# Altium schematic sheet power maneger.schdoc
size 297 x 209 mm; Symbol: Drawing-Symbol_A4; @Project Name: Hưhwwuey; @Page Count: 1; @Update Date: 2026-09-22; @Create Date: 2026-09-22; @Schematic Name: Schematic1; @Page No: 1; @Page Name: P1; Company: EasyEDA.com; Version: V1.0; Page Size: A4; Device: Drawing-Symbol_A4; @Create Time: 21:23:17; @Update Time: 21:23:17; Border: 1; Width: 1170; Height: 825; Region Start: 1; X Region Count: 6; Y Region Count: 4; Blade Width: 10; Title Block Position: 3; @Board Name: Board1
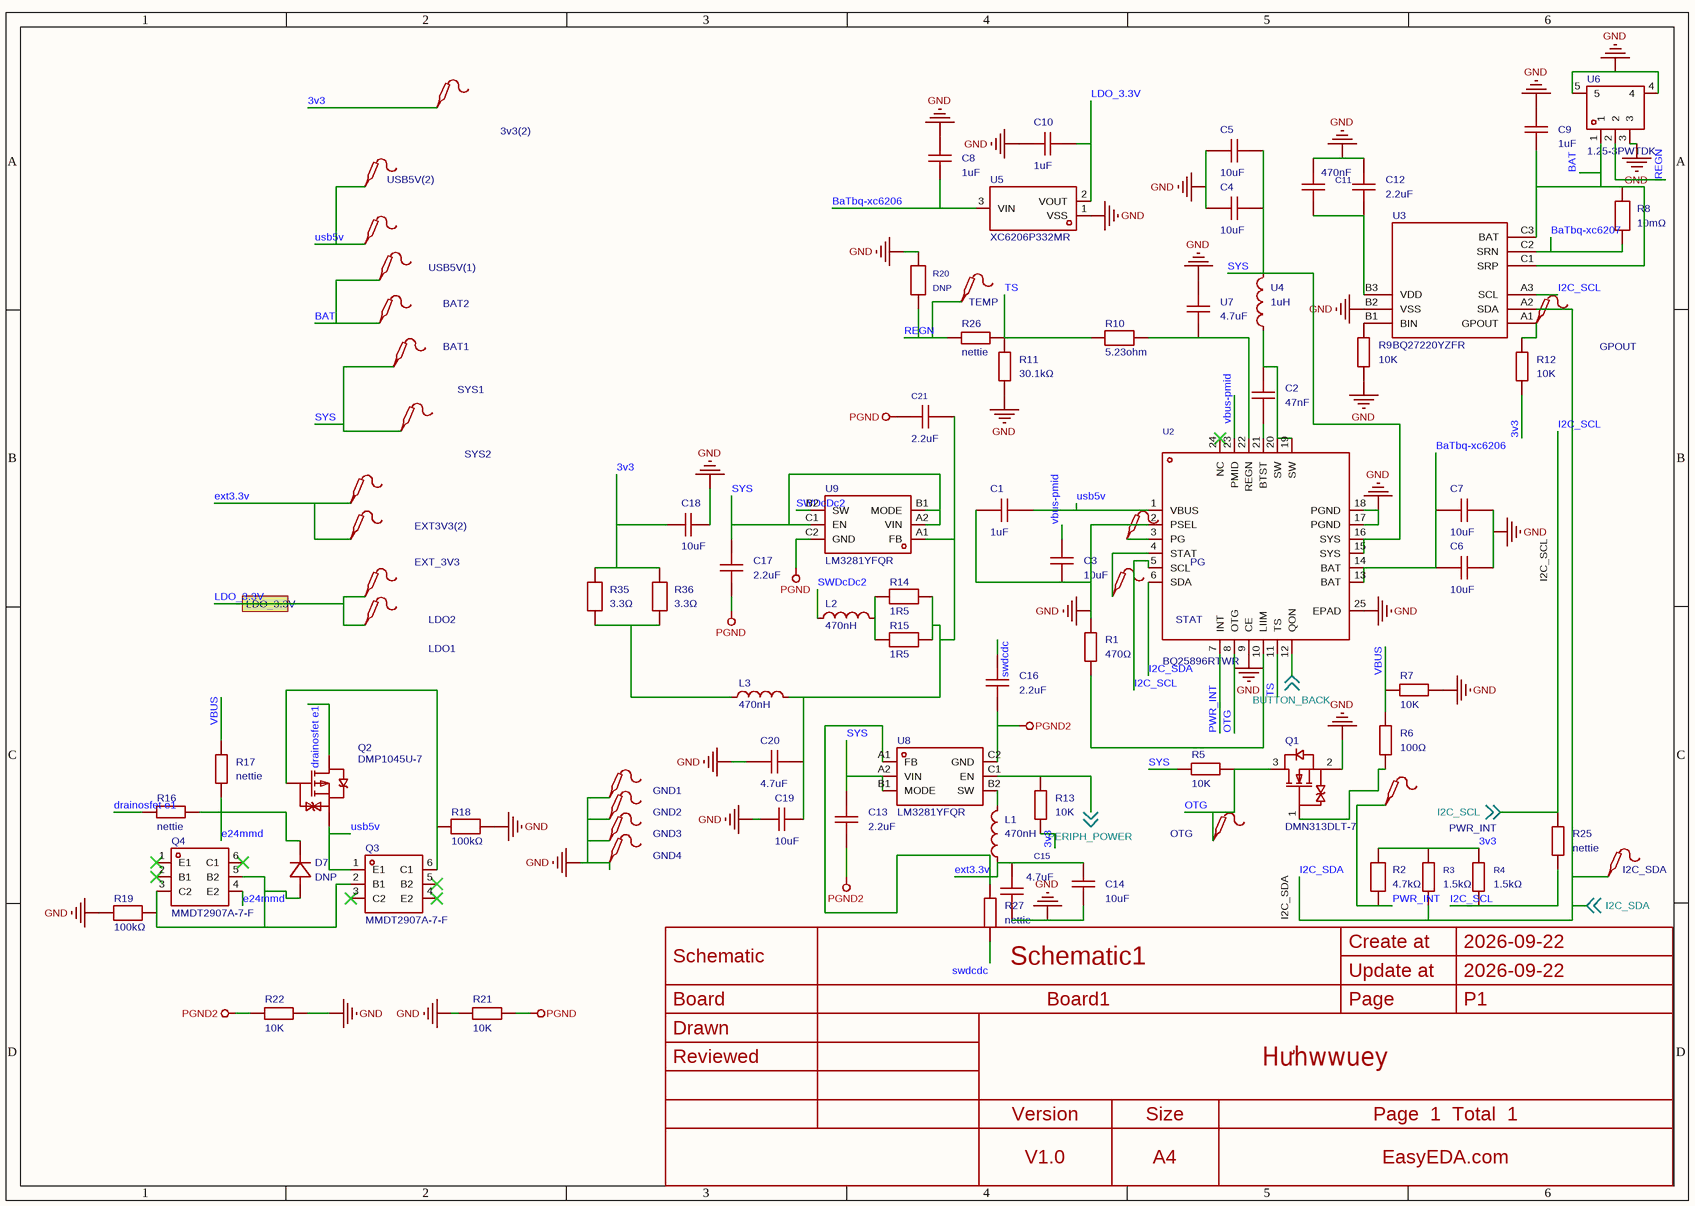
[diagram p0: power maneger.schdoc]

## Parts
3v3(2)  (no value)  [Test-Point-0.5mm]
BAT1  (no value)  [Test-Point-0.5mm]
BAT2  (no value)  [Test-Point-0.5mm]
C1  1uF  [C0603]
C2  47nF  [C0805]
C3  10uF  [C0603]
C4  10uF  [C0603]
C5  10uF  [C0603]
C6  10uF  [C0603]
C7  10uF  [C0603]
C8  1uF  [C0603]
C9  1uF  [C0603]
C10  1uF  [C0603]
C11  470nF  [C0402]
C12  2.2uF  [C0402]
C13  2.2uF  [C0402]
C14  10uF  [C0402]
C15  4.7uF  [C0805]
C16  2.2uF  [C0402]
C17  2.2uF  [C0402]
C18  10uF  [C0402]
C19  10uF  [C0402]
C20  4.7uF  [C1206]
C21  2.2uF  [C0603]
D7  DNP  [SOD-123_L2.7-W1.6-LS3.7-FD]
EXT3V3(2)  (no value)  [Test-Point-0.5mm]
EXT_3V3  (no value)  [Test-Point-0.5mm]
GND1  (no value)  [Test-Point-0.5mm]
GND2  (no value)  [Test-Point-0.5mm]
GND3  (no value)  [Test-Point-0.5mm]
GND4  (no value)  [Test-Point-0.5mm]
GPOUT  (no value)  [Test-Point-0.5mm]
I2C_SDA  (no value)  [Test-Point-0.5mm]
L1  470nH  [L0805]
L2  470nH  [L0805]
L3  470nH  [L0805]
LDO1  (no value)  [Test-Point-0.5mm]
LDO2  (no value)  [Test-Point-0.5mm]
OTG  (no value)  [Test-Point-0.5mm]
PG  (no value)  [Test-Point-0.5mm]
PWR_INT  (no value)  [Test-Point-0.5mm]
Q1  DMN313DLT-7  [SOT-523-3_L1.6-W0.8-P1.00-LS1.6-BR]
Q2  DMP1045U-7  [SOT-23-3_L2.9-W1.3-P1.90-LS2.4-BR]
Q3  MMDT2907A-7-F  [SOT-363_L2.0-W1.3-P0.65-LS2.1-BL]
Q4  MMDT2907A-7-F  [SOT-363_L2.0-W1.3-P0.65-LS2.1-BL]
R1  470Ω  [R0402]
R2  4.7kΩ  [R0402]
R3  1.5kΩ  [R0402]
R4  1.5kΩ  [R0402]
R5  10K  [R0402]
R6  100Ω  [R0402]
R7  10K  [R0402]
R8  10mΩ  [R2512]
R9  10K  [R0402]
R10  5.23ohm  [R1206]
R11  30.1kΩ  [R0402]
R12  10K  [R0402]
R13  10K  [R0402]
R14  1R5  [R1206]
R15  1R5  [R1206]
R16  nettie  [R0402]
R17  nettie  [R0402]
R18  100kΩ  [R0402]
R19  100kΩ  [R0402]
R20  DNP  [R0402]
R21  10K  [R0402]
R22  10K  [R0402]
R25  nettie  [R0402]
R26  nettie  [R0402]
R27  nettie  [R0402]
R35  3.3Ω  [R0402]
R36  3.3Ω  [R0402]
STAT  (no value)  [Test-Point-0.5mm]
SYS1  (no value)  [Test-Point-0.5mm]
SYS2  SYS1  [Test-Point-0.5mm]  (value not drawn)
TEMP  (no value)  [Test-Point-0.5mm]
U2  BQ25896RTWR  [QFN-24_L4.0-W4.0-P0.50-TL-EP2.7]
U3  BQ27220YZFR  [DSBGA-9_L1.7-W1.6-R3-C3-P0.50-BL]
U4  1uH  [L1008]
U5  XC6206P332MR  [SOT-23-3_L3.0-W1.7-P0.95-LS2.9-BR]
U6  1.25-3PWTDK  [CONN-SMD_3P-P1.25_SHOU_1.25-3PWTDK]
U7  4.7uF  [C0402]
U8  LM3281YFQR  [DSBGA-6_L1.4-W1.1-R3-C2-P0.40-BL]
U9  LM3281YFQR  [DSBGA-6_L1.4-W1.1-R3-C2-P0.40-BL]
USB5V(1)  (no value)  [Test-Point-0.5mm]
USB5V(2)  (no value)  [Test-Point-0.5mm]

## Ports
LDO_3.3V (in)

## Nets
GND: C1.1 C3.1 C4.1 C5.1 C6.1 C7.2 C8.2 C9.2 C10.1 C11.2 C12.2 C14.1 C15.1 C18.2 C19.1 C20.1 GND1.1 GND2.1 GND3.1 GND4.1 Q1.2(S) R1.2 R7.2 R9.1 R11.1 R18.2 R19.1 R20.2 R21.1 R22.2 U2.2(PSEL) U2.9(CE) U2.17(PGND) U2.18(PGND) U2.25(EPAD) U3.B2(VSS) U5.1(VSS) U6.3 U6.4 U6.5 U7.2
PGND: C17.1 C21.1 R21.2 U9.C2(GND)
PGND2: C13.1 C16.2 R22.1 U8.C2(GND)
3v3: 3v3(2).1 C18.1 R2.2 R3.2 R4.2 R12.1 R13.1 R35.2 R36.2
BAT: BAT1.1 BAT2.1 C9.1 R8.2 U3.C1(SRP) U3.C3(BAT) U6.1
BaTbq-xc6206: C6.2 C7.1 C8.1 U2.13(BAT) U2.14(BAT) U5.3(VIN)
BaTbq-xc6207: R8.1 U3.C2(SRN)
BUTTON_BACK: U2.12(QON) ; off-sheet BUTTON_BACK
drainosfet e1: Q2.3(D) R16.1
e24mmd: D7.2(-) Q4.4(E2) R16.2 R17.1
ext3.3v: C14.2 C15.2 EXT3V3(2).1 EXT_3V3.1 L1.1 R27.1 U8.A1(FB)
I2C_SCL: R4.1 R25.1 R25.2 U2.5(SCL) U3.A3(SCL) ; off-sheet I2C_SCL
I2C_SDA: I2C_SDA.1 R3.1 U2.6(SDA) U3.A2(SDA) ; off-sheet I2C_SDA
LDO_3.3V: C10.2 LDO1.1 LDO2.1 U5.2(VOUT) ; port LDO_3.3V
OTG: OTG.1 Q1.3(D) R5.2 U2.8(OTG)
PERIPH_POWER: R13.2 U8.C1(EN) ; off-sheet PERIPH_POWER
PWR_INT: PWR_INT.1 R2.1 U2.7(INT)
REGN: R20.1 R26.1 TEMP.1 U6.2
swdcdc: C16.1 R27.2
SWDcDc2: L2.1 U9.B2(SW)
SYS: C4.2 C5.2 C13.2 C17.2 R5.1 SYS1.1 SYS2.1 U2.15(SYS) U2.16(SYS) U4.2 U8.A2(VIN) U8.B1(MODE) U9.A2(VIN) U9.B1(MODE) U9.C1(EN)
TS: R10.1 R11.2 R26.2 U2.11(TS)
usb5v: C1.2 Q2.2(S) Q3.1(E1) U2.1(VBUS) USB5V(1).1 USB5V(2).1
VBUS: R6.2 R7.1 R17.2
vbus-pmid: C3.2 U2.23(PMID)
NetC2_1: C2.1 U2.21(BTST)
NetC2_2: C2.2 U2.19(SW) U2.20(SW) U4.1
NetC11_1: C11.1 C12.1 U3.B3(VDD)
NetC19_2: C19.2 C20.2 C21.2 L3.2 R14.2 R15.2 U9.A1(FB)
NetD7_1: D7.1(+) Q3.2(B1) Q4.3(C2) Q4.5(B2) R19.2
NetGPOUT_1: GPOUT.1 R12.2 U3.A1(GPOUT)
NetL1_2: L1.2 U8.B2(SW)
NetL2_2: L2.2 R14.1 R15.1
NetL3_1: L3.1 R35.1 R36.1
NetPG_1: PG.1 U2.3(PG)
NetQ1_1: Q1.1(G) R6.1
NetQ2_1: Q2.1(G) Q3.6(C1) R18.1
NetR1_1: R1.1 U2.10(LIIM)
NetR9_2: R9.2 U3.B1(BIN)
NetR10_2: R10.2 U2.22(REGN) U7.1
NetSTAT_1: STAT.1 U2.4(STAT)

Not connected (* = marked no-connect by the designer): Q3 3(C2)* 4(E2)* 5(B2)*; Q4 1(E1)* 2(B1)* 6(C1)*; U2 24(NC)*

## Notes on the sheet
- I2C_SCL
- I2C_SDA

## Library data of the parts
3v3(2) BAT1 BAT2 EXT3V3(2) EXT_3V3 GND1-GND4 GPOUT I2C_SDA LDO1 LDO2 OTG PG PWR_INT STAT SYS1 SYS2 TEMP USB5V(1) USB5V(2) = Test-Point: Test Point 测试点; AddInBom: yes
C1 = CL10A105KB8NNNC: Capacitance:1uF Tolerance:±10% Tolerance:±10% Voltage Rating:50V Temperature Coefficient:X5R; Manufacturer: SAMSUNG(三星); AddInBom: yes; ModelId: 624118aa3cc7497086c383c2d72e08520819f05c4eef4c71ace90d822a990e87; ModelName: C0603_L1.6-W0.8-H0.8; ModelTransform: 62.992,31.496,0,0,0,0,0,0,0; Tolerance: ±10%; Voltage Rating: 50V; Temperature Coefficient: X5R
C2 = C0805C473F3GECAUTO7210: Capacitance: Tolerance:±1% Tolerance:±1% Voltage Rated: Temperature Coefficient:; Manufacturer: KEMET(基美); AddInBom: yes; ModelId: 8c88e81f49c6409b980720ec8953afb60819f05c4eef4c71ace90d822a990e87; ModelName: C0805_L2.0-W1.3-H1.3; ModelTransform: 78.74,51.181,0,0,0,0,0,0.0005,0; Tolerance: ±1%
C3 = 0603X106K100: Capacitance:10uF Tolerance:±10% Tolerance:±10% Voltage Rating:10V Temperature Coefficient:X5R; Manufacturer: Walsin(华新科); AddInBom: yes; ModelId: 624118aa3cc7497086c383c2d72e08520819f05c4eef4c71ace90d822a990e87; ModelName: C0603_L1.6-W0.8-H0.8; ModelTransform: 62.992,31.496,0,0,0,0,0,0,0; Tolerance: ±10%; Voltage Rating: 10V; Temperature Coefficient: X5R
C4-C7 = GRM188Z71A106KA73D: Capacitance: Tolerance:±10% Tolerance:±10% Voltage Rated: Temperature Coefficient:; Manufacturer: muRata(村田); AddInBom: yes; ModelId: 624118aa3cc7497086c383c2d72e08520819f05c4eef4c71ace90d822a990e87; ModelName: C0603_L1.6-W0.8-H0.8; ModelTransform: 62.992,31.496,0,0,0,0,0,0,0; Tolerance: ±10%
C8 C9 = UMK107AB7105KA-T: Capacitance:1uF Tolerance:±10% Tolerance:±10% Voltage Rating:50V Temperature Coefficient:X7R; Manufacturer: TAIYO YUDEN(太诱); AddInBom: yes; ModelId: 624118aa3cc7497086c383c2d72e08520819f05c4eef4c71ace90d822a990e87; ModelName: C0603_L1.6-W0.8-H0.8; ModelTransform: 62.992,31.496,0,0,0,0,0,0,0; Tolerance: ±10%; Voltage Rating: 50V; Temperature Coefficient: X7R
C10 = CL10A105KB8NNNC: Capacitance:1uF Tolerance:±10% Tolerance:±10% Voltage Rating:50V Temperature Coefficient:X5R; Manufacturer: SAMSUNG(三星); 3D Model: 624118aa3cc7497086c383c2d72e08520819f05c4eef4c71ace90d822a990e87; 3D Model Transform: 62.992,31.496,0,0,0,0,0,0,0; Tolerance: ±10%; Voltage Rating: 50V; Temperature Coefficient: X5R; AddInBom: yes; ModelName: C0603_L1.6-W0.8-H0.8
C11 = CC0402KRX5R8BB474: Capacitance:470nF Tolerance:±10% Tolerance:±10% Voltage Rating:25V Temperature Coefficient:X5R; Manufacturer: YAGEO(国巨); AddInBom: yes; ModelId: b7d13df3e9464d7a99d0651d1a5b4d570819f05c4eef4c71ace90d822a990e87; ModelName: C0402_L1.0-W0.5-H0.5; ModelTransform: 39.37,19.685,0,0,0,0,0,0,0; Tolerance: ±10%; Voltage Rating: 25V; Temperature Coefficient: X5R
C12 C13 C17 = CC0402KRX5R8BB225: Capacitance:2.2uF Tolerance:±10% Tolerance:±10% Voltage Rating:25V Temperature Coefficient:X5R; Manufacturer: YAGEO(国巨); AddInBom: yes; ModelId: b7d13df3e9464d7a99d0651d1a5b4d570819f05c4eef4c71ace90d822a990e87; ModelName: C0402_L1.0-W0.5-H0.5; ModelTransform: 39.37,19.685,0,0,0,0,0,0,0; Tolerance: ±10%; Voltage Rating: 25V; Temperature Coefficient: X5R
C14 = CL05A106MQ5NUNC: Capacitance:10uF Tolerance:±20% Tolerance:±20% Voltage Rating:6.3V Temperature Coefficient:X5R; Manufacturer: SAMSUNG(三星); AddInBom: yes; ModelId: b7d13df3e9464d7a99d0651d1a5b4d570819f05c4eef4c71ace90d822a990e87; ModelName: C0402_L1.0-W0.5-H0.5; ModelTransform: 39.37,19.685,0,0,0,0,0,0,0; Tolerance: ±20%; Voltage Rating: 6.3V; Temperature Coefficient: X5R
C15 = CC0805KKX5R5BB475: Capacitance:4.7uF Tolerance:±10% Tolerance:±10% Voltage Rating:6.3V Temperature Coefficient:X5R; Manufacturer: YAGEO(国巨); AddInBom: yes; ModelId: 8c88e81f49c6409b980720ec8953afb60819f05c4eef4c71ace90d822a990e87; ModelName: C0805_L2.0-W1.3-H1.3; ModelTransform: 78.74,51.181,0,0,0,0,0,0.0005,0; Tolerance: ±10%; Voltage Rating: 6.3V; Temperature Coefficient: X5R
C16 = 0402X225K6R3CT: Capacitance:2.2uF Tolerance:±10% Tolerance:±10% Voltage Rating:6.3V Temperature Coefficient:X5R; Manufacturer: Walsin(华新科); AddInBom: yes; ModelId: b7d13df3e9464d7a99d0651d1a5b4d570819f05c4eef4c71ace90d822a990e87; ModelName: C0402_L1.0-W0.5-H0.5; ModelTransform: 39.37,19.685,0,0,0,0,0,0,0; Tolerance: ±10%; Voltage Rating: 6.3V; Temperature Coefficient: X5R
C18 C19 = CC0402MRX5R5BB106: Capacitance: Tolerance:±20% Tolerance:±20% Voltage Rated: Temperature Coefficient:; Manufacturer: YAGEO(国巨); AddInBom: yes; ModelId: b7d13df3e9464d7a99d0651d1a5b4d570819f05c4eef4c71ace90d822a990e87; ModelName: C0402_L1.0-W0.5-H0.5; ModelTransform: 39.37,19.685,0,0,0,0,0,0,0; Tolerance: ±20%
C20 = C1206C475K5RACTU: Capacitance:4.7uF Tolerance:±10% Tolerance:±10% Voltage Rating:50V Temperature Coefficient:X7R; Manufacturer: KEMET(基美); AddInBom: yes; ModelId: c6790e9475e1483991d2c64340b24e960819f05c4eef4c71ace90d822a990e87; ModelName: C1206_L3.2-W1.6-H1.3; ModelTransform: 125.984,62.992,0,0,0,0,0,0,0; Tolerance: ±10%; Voltage Rating: 50V; Temperature Coefficient: X7R
C21 = GRM188R71A225KE15D: Capacitance: Tolerance:±10% Tolerance:±10% Voltage Rated: Temperature Coefficient:; Manufacturer: muRata(村田); AddInBom: yes; ModelId: 624118aa3cc7497086c383c2d72e08520819f05c4eef4c71ace90d822a990e87; ModelName: C0603_L1.6-W0.8-H0.8; ModelTransform: 62.992,31.496,0,0,0,0,0,0,0; Tolerance: ±10%
D7 = 1N4148W_C5345962: Diode Configuration:Standalone Pd - Power Dissipation:350mW Current - Rectified:150mA Voltage - DC Reverse(Vr):100V Voltage - Forward(Vf@If):1.25V@150mA Non-Repetitive Peak Forward Surge Current:2A Reverse Leakage Current (Ir):1uA@75V Reverse Recovery Tim; Manufacturer: HXY MOSFET(华轩阳电子); Add into BOM: no; ConvertToPcb: yes; ModelId: b981535734ea4cbf9e7db3f4ae63abf60819f05c4eef4c71ace90d822a990e87; ModelTransform: 145.669,61.024,0,0,0,0,0,0,0; Pd - Power Dissipation: 350mW; Current - Rectified: 150mA; Voltage - DC Reverse(Vr): 100V; Non-Repetitive Peak Forward Surge Current: 2A; Reverse Recovery Time (trr): 4ns; Operating Junction Temperature Range: -55℃~+150℃
L1 L2 = DFE201210U-R47M=P2: Inductance:470nH Tolerance:±20% Tolerance:±20% Current Rating:3A Current - Saturation(Isat):4.4A DC Resistance(DCR):42mΩ; Manufacturer: muRata(村田); AddInBom: yes; ModelId: b83c7c5430874b8eb2319a65d94334290819f05c4eef4c71ace90d822a990e87; ModelName: R0805_L2.0-W1.3-H0.6; ModelTransform: 78.74,51.181,0,0,0,0,0,0.001,0; Tolerance: ±20%; Current Rating: 3A; Current - Saturation(Isat): 4.4A; DC Resistance(DCR): 42mΩ
L3 = DFE201210U-R47M=P2: Inductance:470nH Tolerance:±20% Tolerance:±20% Current Rating:3A Current - Saturation(Isat):4.4A DC Resistance(DCR):42mΩ; Manufacturer: muRata(村田); 3D Model: b83c7c5430874b8eb2319a65d94334290819f05c4eef4c71ace90d822a990e87; 3D Model Transform: 78.74,51.181,0,0,0,0,0,0.001,0; Tolerance: ±20%; Current Rating: 3A; Current - Saturation(Isat): 4.4A; DC Resistance(DCR): 42mΩ; AddInBom: yes; ModelName: R0805_L2.0-W1.3-H0.6
Q1 = DMN313DLT-7: Number:1 N-channel Drain to Source Voltage:30V Current - Continuous Drain(Id):310mA RDS(on):3.2Ω@2.5V Pd - Power Dissipation:360mW Gate Threshold Voltage (Vgs(th)):1.5V Gate Charge(Qg):500pC@4.5V Input Capacitance(Ciss):36.3pF Reverse Transfer Capacitance; Manufacturer: DIODES(美台); AddInBom: yes; ModelId: 1cc59aa5ffe4420193f3c1f87584e8b70819f05c4eef4c71ace90d822a990e87; ModelName: SOT-523-3P_L1.6-W0.8-H0.9-LS1.6-P0.50; ModelTransform: 63.48633,62.992,0,180,0,0,0,0,0; Drain to Source Voltage: 30V; Current - Continuous Drain(Id): 310mA; Pd - Power Dissipation: 360mW; Gate Threshold Voltage (Vgs(th)): 1.5V; Input Capacitance(Ciss): 36.3pF; Reverse Transfer Capacitance (Crss@Vds): 4.7pF; Output Capacitance(Coss): 7.6pF
Q2 = DMP1045U-7: Number:1 P-Channel Drain to Source Voltage:12V Current - Continuous Drain(Id):5.2A RDS(on):31mΩ@4.5V Pd - Power Dissipation:1.3W Gate Threshold Voltage (Vgs(th)):1V Gate Charge(Qg):15.8nC@4.5V Input Capacitance(Ciss):1.357nF Reverse Transfer Capacitance (; Manufacturer: DIODES(美台); AddInBom: yes; ModelId: 62a57c6760504a01965db6419a6d07df0819f05c4eef4c71ace90d822a990e87; ModelName: SOT-23-3P_L2.9-W1.3-H1.0-LS2.4-P0.95; ModelTransform: 98.425,114.173,0,180,0,0,0.0005,-0.0005,0; Drain to Source Voltage: 12V; Current - Continuous Drain(Id): 5.2A; Pd - Power Dissipation: 1.3W; Gate Threshold Voltage (Vgs(th)): 1V; Reverse Transfer Capacitance (Crss@Vds): 235pF; Output Capacitance(Coss): 504pF; Vgs: ±8V
Q3 Q4 = MMDT2907A-7-F: type:PNP Current - Collector(Ic):600mA Collector - Emitter Voltage VCEO:60V Pd - Power Dissipation:200mW DC Current Gain:100 DC Current Gain:100 Transition frequency(fT):200MHz Current - Collector Cutoff:10uA Vce Saturation(VCE(sat)):1.6V Operating Temper; Manufacturer: DIODES(美台); AddInBom: yes; ModelId: 9c651890c14f4164885657d2cfe1b0c60819f05c4eef4c71ace90d822a990e87; ModelName: SOT-363-6P_L2.0-W1.3-H1.1-LS2.0-P0.65; ModelTransform: 78.74,82.677,0,0,0,0,0,0,0; type: PNP; Current - Collector(Ic): 600mA; Collector - Emitter Voltage VCEO: 60V; Pd - Power Dissipation: 200mW; DC Current Gain: 100; Transition frequency(fT): 200MHz; Current - Collector Cutoff: 10uA; Vce Saturation(VCE(sat)): 1.6V; Emitter-Base Voltage(Vebo): 5V; Number: 2 PNP
R1 = WR04X471JTL: Type:Thick Film Resistor Resistance:470Ω Tolerance:±5% Tolerance:±5% Power(Watts):62.5mW Voltage-Supply(Max):50V Temperature Coefficient:±100ppm/℃ Temperature Coefficient:±100ppm/℃ Operating Temperature:-55℃~+155℃ Operating Temperature:-55℃~+155℃; Manufacturer: Walsin(华新科); AddInBom: yes; ModelId: efdecb7dae4442949d28eecaf748420f0819f05c4eef4c71ace90d822a990e87; ModelName: R0402_L1.0-W0.5-H0.4; ModelTransform: 39.37,19.685,0,0,0,0,0,0,0; Tolerance: ±5%; Power(Watts): 62.5mW; Voltage-Supply(Max): 50V
R2 = WR04X472JTL_C384327: Type:Thick Film Resistor Resistance:4.7kΩ Tolerance:±5% Tolerance:±5% Power(Watts):62.5mW Voltage-Supply(Max):50V Temperature Coefficient:±100ppm/℃ Temperature Coefficient:±100ppm/℃ Operating Temperature:-55℃~+155℃ Operating Temperature:-55℃~+155℃; Manufacturer: Walsin(华新科); AddInBom: yes; ModelId: efdecb7dae4442949d28eecaf748420f0819f05c4eef4c71ace90d822a990e87; ModelName: R0402_L1.0-W0.5-H0.4; ModelTransform: 39.37,19.685,0,0,0,0,0,0,0; Tolerance: ±5%; Power(Watts): 62.5mW; Voltage-Supply(Max): 50V
R3 R4 = 0402WGF1501TCE: Type:Thick Film Resistors Resistance:1.5kΩ Tolerance:±1% Tolerance:±1% Power(Watts): Overload Voltage (Max): Temperature Coefficient:±100ppm/℃ Temperature Coefficient:±100ppm/℃ Operating Temperature Range:-55℃~+155℃ Operating Temperature Range:-55℃~+155℃; Manufacturer: UNI-ROYAL(厚声); AddInBom: yes; ModelId: efdecb7dae4442949d28eecaf748420f0819f05c4eef4c71ace90d822a990e87; ModelName: R0402_L1.0-W0.5-H0.4; ModelTransform: 39.37,19.685,0,0,0,0,0,0,0; Tolerance: ±1%
R5 R7 = Res_0402: Symbol: Res; ConvertToPcb: yes; ModelId: efdecb7dae4442949d28eecaf748420f0819f05c4eef4c71ace90d822a990e87; ModelName: R0402_L1.0-W0.5-H0.4; ModelTransform: 39.37,19.685,0,0,0,0,0,0,0
R6 = RC-02W101JT: Type:Thick Film Resistor Resistance:100Ω Tolerance:±5% Tolerance:±5% Power(Watts):62.5mW Voltage-Supply(Max):50V Temperature Coefficient:±200ppm/℃ Temperature Coefficient:±200ppm/℃ Operating Temperature:-55℃~+155℃ Operating Temperature:-55℃~+155℃; Manufacturer: FH(风华); AddInBom: yes; ModelId: efdecb7dae4442949d28eecaf748420f0819f05c4eef4c71ace90d822a990e87; ModelName: R0402_L1.0-W0.5-H0.4; ModelTransform: 39.37,19.685,0,0,0,0,0,0,0; Tolerance: ±5%; Power(Watts): 62.5mW; Voltage-Supply(Max): 50V
R8 = RE2512F3R010: Type:Current Sense Resistor；Alloy Resistor Resistance:10mΩ Tolerance:±1% Tolerance:±1% Power(Watts):3W Temperature Coefficient:±50ppm/℃ Temperature Coefficient:±50ppm/℃ Mounting Type:SMD; Manufacturer: JIERR(捷而瑞); AddInBom: yes; ModelId: c704f12ea0da45b6b9e7d0ddac98e7f70819f05c4eef4c71ace90d822a990e87; ModelName: R2512_L6.3-W3.2-H0.6; ModelTransform: 248.031,125.984,0,0,0,0,-0.0005,0,0; Tolerance: ±1%; Power(Watts): 3W
R9 R12 R13 = Res_0402: Symbol: Res; 3D Model: efdecb7dae4442949d28eecaf748420f0819f05c4eef4c71ace90d822a990e87; 3D Model Transform: 39.37,19.685,0,0,0,0,0,0,0; ConvertToPcb: yes; ModelName: R0402_L1.0-W0.5-H0.4
R10 = SCR1206JR120: Type:Thick Film Resistor Resistance:120mΩ Tolerance:±5% Tolerance:±5% Power(Watts):250mW Voltage-Supply(Max):200V Temperature Coefficient:- Temperature Coefficient:- Operating Temperature:-55℃~+155℃ Operating Temperature:-55℃~+155℃; Manufacturer: VO(翔胜); Convert to PCB: yes; Add into BOM: no; ModelId: 04f48aacb8114155959811d2338bbb060819f05c4eef4c71ace90d822a990e87; ModelName: R1206_L3.2-W1.6-H0.6; ModelTransform: 125.984,62.992,0,0,0,0,0,0,0; Tolerance: ±5%; Power(Watts): 250mW; Voltage-Supply(Max): 200V
R11 = WR04X3012FTL: Type:Thick Film Resistor Resistance:30.1kΩ Tolerance:±1% Tolerance:±1% Power(Watts):62.5mW Voltage-Supply(Max):50V Temperature Coefficient:±100ppm/℃ Temperature Coefficient:±100ppm/℃ Operating Temperature:-55℃~+155℃ Operating Temperature:-55℃~+155℃; Manufacturer: Walsin(华新科); AddInBom: yes; ModelId: efdecb7dae4442949d28eecaf748420f0819f05c4eef4c71ace90d822a990e87; ModelName: R0402_L1.0-W0.5-H0.4; ModelTransform: 39.37,19.685,0,0,0,0,0,0,0; Tolerance: ±1%; Power(Watts): 62.5mW; Voltage-Supply(Max): 50V
R14 R15 = SCR1206JR120: Type:Thick Film Resistor Resistance:120mΩ Tolerance:±5% Tolerance:±5% Power(Watts):250mW Voltage-Supply(Max):200V Temperature Coefficient:- Temperature Coefficient:- Operating Temperature:-55℃~+155℃ Operating Temperature:-55℃~+155℃; Manufacturer: VO(翔胜); Add into BOM: no; Convert to PCB: yes; ModelId: 04f48aacb8114155959811d2338bbb060819f05c4eef4c71ace90d822a990e87; ModelName: R1206_L3.2-W1.6-H0.6; ModelTransform: 125.984,62.992,0,0,0,0,0,0,0; Tolerance: ±5%; Power(Watts): 250mW; Voltage-Supply(Max): 200V
R16 R26 = Res_0402: Symbol: Res; 3D Model: efdecb7dae4442949d28eecaf748420f0819f05c4eef4c71ace90d822a990e87; 3D Model Transform: 39.37,19.685,0,0,0,0,0,0,0; Add into BOM: no; ConvertToPcb: yes; ModelName: R0402_L1.0-W0.5-H0.4
R17 R21 R22 R25 R27 = Res_0402: Symbol: Res; Add into BOM: no; 3D Model: efdecb7dae4442949d28eecaf748420f0819f05c4eef4c71ace90d822a990e87; 3D Model Transform: 39.37,19.685,0,0,0,0,0,0,0; ConvertToPcb: yes; ModelName: R0402_L1.0-W0.5-H0.4
R18 R19 = SCR0402J100K: Type:Thick Film Resistor Resistance:100kΩ Tolerance:±5% Tolerance:±5% Power(Watts):62.5mW Voltage-Supply(Max):50V Operating Temperature:-55℃~+155℃ Operating Temperature:-55℃~+155℃; Manufacturer: VO(翔胜); AddInBom: yes; ModelId: efdecb7dae4442949d28eecaf748420f0819f05c4eef4c71ace90d822a990e87; ModelName: R0402_L1.0-W0.5-H0.4; ModelTransform: 39.37,19.685,0,0,0,0,0,0,0; Tolerance: ±5%; Power(Watts): 62.5mW; Voltage-Supply(Max): 50V
R20 = SCR0402F6R04: Type:Thick Film Resistor Resistance:6.04Ω Tolerance:±1% Tolerance:±1% Power(Watts):62.5mW Voltage-Supply(Max):50V Temperature Coefficient:±400ppm/℃ Temperature Coefficient:±400ppm/℃ Operating Temperature:-55℃~+155℃ Operating Temperature:-55℃~+155℃; Manufacturer: VO(翔胜); 3D Model: efdecb7dae4442949d28eecaf748420f0819f05c4eef4c71ace90d822a990e87; 3D Model Transform: 39.37,19.685,0,0,0,0,0,0,0; Tolerance: ±1%; Power(Watts): 62.5mW; Voltage-Supply(Max): 50V; Add into BOM: no; ConvertToPcb: yes; ModelName: R0402_L1.0-W0.5-H0.4
R35 R36 = SCR0402J3R3: Type:Thick Film Resistor Resistance:3.3Ω Tolerance:±5% Tolerance:±5% Power(Watts):62.5mW Voltage-Supply(Max):50V Temperature Coefficient:±400ppm/℃ Temperature Coefficient:±400ppm/℃ Operating Temperature:-55℃~+155℃ Operating Temperature:-55℃~+155℃; Manufacturer: VO(翔胜); AddInBom: yes; ModelId: efdecb7dae4442949d28eecaf748420f0819f05c4eef4c71ace90d822a990e87; ModelName: R0402_L1.0-W0.5-H0.4; ModelTransform: 39.37,19.685,0,0,0,0,0,0,0; Tolerance: ±5%; Power(Watts): 62.5mW; Voltage-Supply(Max): 50V
U2 = BQ25896RTWR: The Chip Type:Charging IC Voltage - Supply:3.9V~14V Voltage - Supply:3.9V~14V Charge Current - Max:3A Charging Saturation Voltage:4.208V End-Off Voltage:- Type of Battery:Lithium Battery Number of Cells:1 Number of Cells:1 Operating Temperature:-40℃~+85℃; Manufacturer: TI(德州仪器); AddInBom: yes; ModelId: d78f0056219c4c74a64797dd00480d510819f05c4eef4c71ace90d822a990e87; ModelTransform: 158.267,158.267,0,0,0,0,0,0,0; Charge Current - Max: 3A; Charging Saturation Voltage: 4.208V; Number of Cells: 1; Battery Temperature Detection: Support; Supply Current (Iq): 12uA; Interface: I2C
U3 = BQ27220YZFR: The Chip Type:Monitoring IC Voltage - Supply:2.45V~4.5V Voltage - Supply:2.45V~4.5V Charge Current - Max:- Charging Saturation Voltage:- End-Off Voltage:- Type of Battery:Lithium Battery Number of Cells:1 Number of Cells:1 Operating Temperature:-40℃~+85℃; Manufacturer: TI(德州仪器); AddInBom: yes; ModelId: e5c3e2eaf25b46c1a86920be8108c4b70819f05c4eef4c71ace90d822a990e87; ModelName: DSBGA-9_L1.7-W1.6-H0.6-R3-C3-P0.50-BL; ModelTransform: 63.7794,62.2046,0,0,0,0,-0.0045,-6.625,0; Number of Cells: 1; Battery Temperature Detection: Support; Supply Current (Iq): 50uA; Interface: I2C
U4 = DFE252012P-1R0M=P2: Inductance:1uH Tolerance:±20% Tolerance:±20% Current Rating:4.3A Current - Saturation(Isat):4.3A DC Resistance(DCR):42mΩ Type:- Ratings:-; Manufacturer: muRata(村田); AddInBom: yes; ModelId: 5863d20e5e24416daeee77ca5366400d0819f05c4eef4c71ace90d822a990e87; ModelTransform: 98.425,78.74,0,0,0,0,0,0,0; Tolerance: ±20%; Current Rating: 4.3A; DC Resistance(DCR): 42mΩ
U5 = XC6206P332MR_C347376: Output Configuration:Positive Voltage - Supply:8V Output Voltage:3.3V Output Voltage:3.3V Output Current:250mA Power Supply Rejection Ratio (PSRR):40dB@(1kHz) Voltage Dropout:240mV@(50mA) standby current:7uA Noise:- Features:Over Current Protection；Short; Manufacturer: UMW(友台半导体); AddInBom: yes; ModelId: 4eed685bb9f4439b846746bc2193f3c00819f05c4eef4c71ace90d822a990e87; ModelName: SOT-23-3L_L2.9-W1.6-H1.1-LS2.8-P0.95; ModelTransform: 114.173,110.236,0,90,0,0,0,0,0; Voltage - Supply: 8V; Output Voltage: 3.3V; Output Current: 250mA; standby current: 7uA; Output Type: Fixed; Number of Outputs: 1
U6 = 1.25-3PWTDK: Pins Structure:1x3P Pitch:1.25mm Mounting Type:Surface Mount, Right Angle Reference Series:GH Number of Pins:3P Number of Rows:1 Number of PINs Per Row:3 Row Spacing:- Current Rating:1A Contact Material:Phosphor bronze Contact Plating:Tin Operating Temper; Manufacturer: SHOU HAN(首韩); AddInBom: yes; ModelId: 316b2dbff8e14b7e9996857d48ad2e940819f05c4eef4c71ace90d822a990e87; ModelTransform: 275.59,191.3382,0,0,0,0,0,-16.733,0; Pins Structure: 1x3P; Pitch: 1.25mm; Reference Series: GH; Number of PINs Per Row: 3; Current Rating: 1A; Voltage Rating: 125V; Plastic Material: LCP; Flame Retardant Rating: UL94V-0
U7 = CC0402MRX5R7BB475: Capacitance:4.7uF Tolerance:±20% Tolerance:±20% Voltage Rating:16V Temperature Coefficient:X5R; Manufacturer: YAGEO(国巨); AddInBom: yes; ModelId: b7d13df3e9464d7a99d0651d1a5b4d570819f05c4eef4c71ace90d822a990e87; ModelName: C0402_L1.0-W0.5-H0.5; ModelTransform: 39.37,19.685,0,0,0,0,0,0,0; Tolerance: ±20%; Voltage Rating: 16V; Temperature Coefficient: X5R
U8 U9 = LM3281YFQR: Function:Step-down type Voltage - Supply:3V~5.5V Voltage - Supply:3V~5.5V Output Voltage:3.3V Output Voltage:3.3V Output Current:1.2A Frequency - Switching:6MHz Frequency - Switching:6MHz Operating Temperature:-30℃~+90℃@(TA) Operating Temperature:-30℃~+90; Manufacturer: TI(德州仪器); AddInBom: yes; ModelId: 2f132dc33d1444e79592ef8e3aa75b6e0819f05c4eef4c71ace90d822a990e87; ModelTransform: 55.118,43.307,0,0,0,0,0,0,0; Output Voltage: 3.3V; Output Current: 1.2A; Frequency - Switching: 6MHz; Number of Outputs: 1; Topology: Buck; Quiescent Current: 16uA; Switch tube (built-in/external): Built-in; Output Type: Fixed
